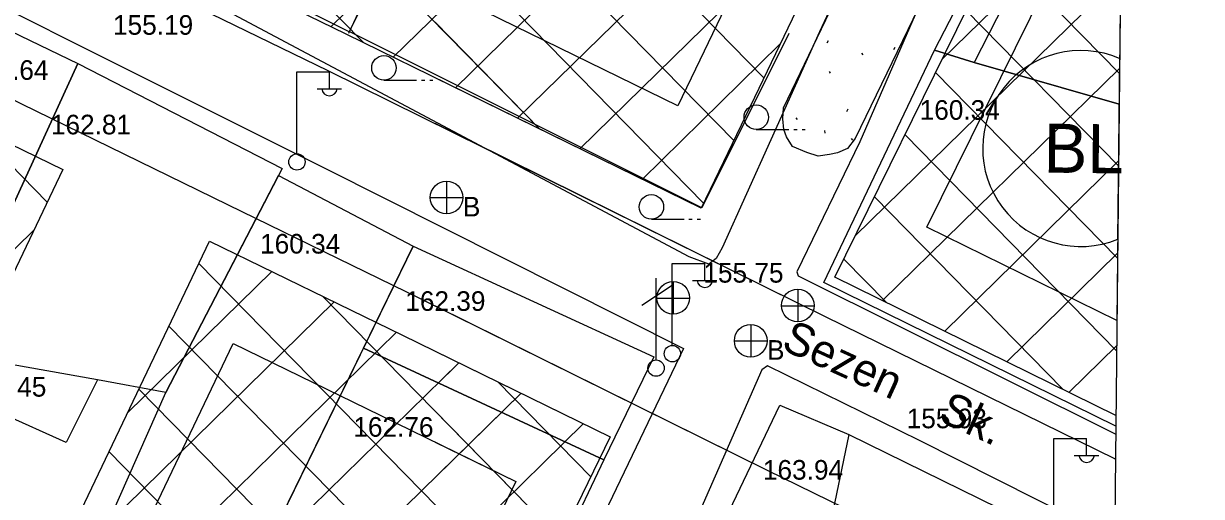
# Model space of a CAD drawing. Extents: x 419677 to 421689, y 4450851 to 4452923.
# Drawn here: x 420633.2 to 420705.3, y 4451724.9 to 4451753.9 of the extents above; entities that cross this region are included whole.
import ezdxf

# ---------------------------------------------------------------- set-up
doc = ezdxf.new("R2010")
doc.units = 0
for name, color, linetype in [('AA_HH', 7, 'Continuous'), ('Level 1', 7, 'Continuous'), ('Level 20', 7, 'Continuous'), ('Level 27', 7, 'Continuous'), ('Level 31', 7, 'Continuous'), ('Level 34', 7, 'Continuous'), ('Level 41', 7, 'Continuous'), ('Level 62', 7, 'Continuous')]:
    doc.layers.add(name, color=color, linetype=linetype)

msp = doc.modelspace()

# ---------------------------------------------------------------- linework, layer by layer
at = {"layer": 'AA_HH'}
for p, q in [((420649.91, 4451745.932), (420649.91, 4451750.932)), ((420649.91, 4451750.932), (420651.91, 4451750.932)), ((420651.91, 4451749.932), (420651.91, 4451750.932)), ((420655.248, 4451750.415), (420657.248, 4451750.415)), ((420657.548, 4451750.415), (420657.748, 4451750.415)), ((420658.048, 4451750.415), (420658.248, 4451750.415)), ((420651.15, 4451749.892), (420652.65, 4451749.892)), ((420678.037, 4451747.395), (420680.037, 4451747.395)), ((420680.337, 4451747.395), (420680.537, 4451747.395)), ((420680.837, 4451747.395), (420681.037, 4451747.395)), ((420659.08, 4451744.231), (420659.08, 4451742.231)), ((420658.08, 4451743.231), (420660.08, 4451743.231)), ((420671.617, 4451741.908), (420673.617, 4451741.908)), ((420673.917, 4451741.908), (420674.117, 4451741.908)), ((420674.417, 4451741.908), (420674.617, 4451741.908)), ((420672.892, 4451734.196), (420672.892, 4451739.196)), ((420672.892, 4451739.196), (420674.892, 4451739.196)), ((420674.892, 4451738.196), (420674.892, 4451739.196)), ((420671.025, 4451736.636), (420672.955, 4451737.906)), ((420671.915, 4451733.286), (420671.915, 4451738.286)), ((420672.97, 4451736.083), (420672.97, 4451738.083)), ((420674.132, 4451738.156), (420675.632, 4451738.156)), ((420671.95, 4451737.073), (420673.95, 4451737.073)), ((420680.591, 4451735.613), (420680.591, 4451737.613)), ((420679.571, 4451736.603), (420681.571, 4451736.603)), ((420677.694, 4451735.46), (420677.694, 4451733.46)), ((420676.694, 4451734.46), (420678.694, 4451734.46)), ((420696.256, 4451723.485), (420696.256, 4451728.485)), ((420696.256, 4451728.485), (420698.256, 4451728.485)), ((420698.256, 4451727.485), (420698.256, 4451728.485)), ((420697.496, 4451727.445), (420698.996, 4451727.445))]:
    msp.add_line(p, q, dxfattribs=at)
for points in [[(420173.096, 4452234.536), (420705.284, 4452228.915), (420698.004, 4451534.891), (420165.768, 4451540.511)], [(420648.295, 4451676.593), (420641.223, 4451662.384), (420640.948, 4451662.031), (420640.508, 4451661.684), (420639.471, 4451661.193), (420638.746, 4451661.186), (420637.534, 4451661.359), (420636.786, 4451661.616), (420584.365, 4451691.657), (420560.63, 4451705.916), (420560.087, 4451706.396), (420559.803, 4451706.768), (420559.709, 4451707.858), (420560.927, 4451712.656), (420582.242, 4451758.178), (420589.137, 4451774.928), (420589.939, 4451775.263), (420617.918, 4451761.909), (420651.635, 4451745.031), (420673.572, 4451733.995), (420661.481, 4451708.765)], [(420636.513, 4451751.427), (420628.393, 4451733.73), (420625.042, 4451735.223), (420626.983, 4451739.07), (420616.108, 4451744.228), (420624.114, 4451757.425)], [(420649.016, 4451745.006), (420641.901, 4451731.298), (420637.717, 4451732.073), (420628.393, 4451733.73), (420636.513, 4451751.427)], [(420657.028, 4451740.247), (420646.913, 4451719.502), (420639.225, 4451723.302), (420638.509, 4451723.641), (420641.901, 4451731.298), (420648.794, 4451744.577)], [(420657.028, 4451740.247), (420671.76, 4451733.483), (420668.7, 4451727.182), (420653.986, 4451734.008)], [(420668.7, 4451727.182), (420661.791, 4451712.61), (420646.913, 4451719.502), (420653.986, 4451734.008)], [(420627.985, 4451731.742), (420621.242, 4451717.589), (420632.959, 4451711.573), (420639.225, 4451723.302), (420638.509, 4451723.641), (420641.901, 4451731.298), (420637.717, 4451732.073), (420635.795, 4451728.243)], [(420695.132, 4451723.104), (420693.277, 4451717.205), (420694.151, 4451716.879), (420692.934, 4451712.965), (420691.908, 4451713.454), (420690.129, 4451708.064), (420686.874, 4451709.515), (420678.21, 4451713.339), (420672.76, 4451716.185), (420674.826, 4451720.778), (420679.47, 4451730.516), (420683.697, 4451728.716)], [(420679.47, 4451730.516), (420683.697, 4451728.716), (420681.53, 4451718.321), (420674.826, 4451720.778)]]:
    msp.add_lwpolyline(points, close=True, dxfattribs=at)
for points in [[(420700.616, 4451783.946), (420684.365, 4451746.633), (420680.51, 4451738.681), (420680.601, 4451738.437), (420700.037, 4451728.745)], [(420695.146, 4451781.793), (420681.899, 4451753.381), (420675.945, 4451740.147), (420675.583, 4451739.5), (420675.132, 4451739.156), (420673.927, 4451739.598), (420644.125, 4451755.472)], [(420663.087, 4451773.536), (420653.124, 4451753.378), (420644.155, 4451757.883)], [(420700.249, 4451748.952), (420691.368, 4451751.492), (420688.935, 4451752.246), (420699.241, 4451772.177), (420700.491, 4451772.027)], [(420700.463, 4451769.316), (420691.368, 4451751.492), (420700.249, 4451748.952)], [(420680.022, 4451753.271), (420674.708, 4451742.607), (420653.112, 4451753.384)], [(420700.043, 4451729.235), (420682.17, 4451738.034), (420688.935, 4451752.246), (420691.368, 4451751.492), (420700.249, 4451748.952)], [(420699.97, 4451722.333), (420688.018, 4451728.351), (420678.731, 4451732.918), (420678.383, 4451732.69), (420658.67, 4451687.779), (420649.079, 4451666.635), (420647.144, 4451660.397), (420646.984, 4451659.823), (420646.876, 4451659.026), (420646.895, 4451658.404), (420647.192, 4451657.734), (420647.879, 4451656.769), (420649.003, 4451655.689), (420652.065, 4451653.381), (420666.641, 4451646.892), (420671.103, 4451645.56), (420671.438, 4451644.757)]]:
    msp.add_lwpolyline(points, dxfattribs=at)
for centre, radius in [((420655.248, 4451751.165), 0.75), ((420678.037, 4451748.145), 0.75), ((420649.92, 4451745.407), 0.5), ((420659.08, 4451743.231), 1), ((420671.617, 4451742.658), 0.75), ((420672.955, 4451737.091), 1), ((420680.575, 4451736.621), 1), ((420677.694, 4451734.46), 1), ((420672.902, 4451733.672), 0.5), ((420671.905, 4451732.786), 0.501)]:
    msp.add_circle(centre, radius, dxfattribs=at)
for centre in [(420651.91, 4451749.935), (420674.892, 4451738.2), (420698.256, 4451727.489)]:
    msp.add_arc(centre, 0.474, 184.83843, 355.14641, dxfattribs=at)
at = {"layer": 'Level 1'}
msp.add_lwpolyline([(420653.094, 4451753.295), (420659.449, 4451766.863), (420661.936, 4451772.145)], dxfattribs=at)
at = {"layer": 'Level 20'}
for points in [[(420682.582, 4451768.29), (420674.58, 4451751.638), (420673.235, 4451748.839)], [(420682.582, 4451768.29), (420674.58, 4451751.638), (420673.235, 4451748.839)], [(420700.11, 4451735.71), (420688.482, 4451741.421), (420698.428, 4451761.571), (420700.372, 4451760.598)], [(420700.11, 4451735.71), (420688.482, 4451741.421), (420698.428, 4451761.571), (420700.372, 4451760.598)], [(420700.372, 4451760.598), (420700.11, 4451735.71)], [(420673.235, 4451748.839), (420658.753, 4451755.946)], [(420673.235, 4451748.839), (420658.753, 4451755.946)], [(420640.31, 4451722.34), (420646.02, 4451734.294)], [(420646.02, 4451734.294), (420654.182, 4451730.311), (420663.324, 4451725.846)], [(420658.373, 4451728.264), (420663.324, 4451725.846)], [(420663.324, 4451725.846), (420661.053, 4451721.162), (420659.275, 4451717.454)], [(420663.324, 4451725.846), (420661.053, 4451721.162), (420659.275, 4451717.454)]]:
    msp.add_lwpolyline(points, dxfattribs=at)
at = {"layer": 'Level 27'}
msp.add_line((420700.049, 4451729.897), (420682.85, 4451738.349), dxfattribs=at)
msp.add_line((420700.049, 4451729.897), (420682.85, 4451738.349), dxfattribs=at)
for points in [[(420698.02, 4451791.59), (420687.354, 4451768.985), (420678.185, 4451749.905), (420674.66, 4451742.57)], [(420698.02, 4451791.59), (420687.354, 4451768.985), (420678.185, 4451749.905), (420674.66, 4451742.57)], [(420682.85, 4451738.349), (420696.412, 4451765.911), (420700.515, 4451774.286)], [(420682.85, 4451738.349), (420696.412, 4451765.911), (420700.515, 4451774.286)], [(420674.66, 4451742.57), (420652.925, 4451753.236), (420642.195, 4451758.464), (420640.315, 4451759.336), (420631.025, 4451763.884), (420628.336, 4451765.146), (420619.63, 4451769.43)], [(420588.3, 4451768.02), (420608.745, 4451758.036), (420621.095, 4451752.014), (420635.592, 4451744.945)], [(420674.66, 4451742.57), (420658.373, 4451750.563)], [(420635.592, 4451744.945), (420628.635, 4451730.385), (420626.405, 4451725.725), (420609.394, 4451733.403), (420599.163, 4451738.124), (420597.92, 4451735.56), (420589.963, 4451719.505), (420594.742, 4451716.488), (420597.726, 4451714.354), (420600.274, 4451712.736)], [(420638.066, 4451712.736), (420640.622, 4451718.135), (420635.442, 4451721.43), (420644.58, 4451740.56)], [(420644.58, 4451740.56), (420656.375, 4451734.804), (420669.1, 4451728.59)], [(420658.373, 4451733.829), (420669.1, 4451728.59)], [(420669.1, 4451728.59), (420664.656, 4451719.425), (420661.515, 4451712.875), (420657.498, 4451703.95)], [(420669.1, 4451728.59), (420664.656, 4451719.425), (420661.515, 4451712.875), (420658.373, 4451705.894)]]:
    msp.add_lwpolyline(points, dxfattribs=at)
at = {"layer": 'Level 31'}
msp.add_lwpolyline([(420700.163, 4451740.676), (420700.279, 4451751.738)], dxfattribs=at)
msp.add_arc((420697.895, 4451746.231), 6, 66.59493, 292.20315, dxfattribs=at)
msp.add_arc((420697.895, 4451746.231), 6, 66.59493, 292.20315, dxfattribs=at)
at = {"layer": 'Level 34'}
for p, q in [((420652.004, 4451753.685), (420693.019, 4451793.868)), ((420655.815, 4451751.818), (420696.92, 4451792.091)), ((420664.78, 4451747.419), (420627.457, 4451785.513)), ((420674.815, 4451742.892), (420633.299, 4451785.266)), ((420674.815, 4451742.892), (420633.299, 4451785.266)), ((420659.623, 4451749.949), (420694.491, 4451784.111)), ((420659.623, 4451749.949), (420694.491, 4451784.111)), ((420653.994, 4451752.711), (420625.599, 4451781.694)), ((420676.657, 4451746.726), (420643.184, 4451780.893)), ((420676.657, 4451746.726), (420643.184, 4451780.893)), ((420678.5, 4451750.561), (420653.348, 4451776.233)), ((420678.5, 4451750.561), (420653.348, 4451776.233)), ((420663.431, 4451748.08), (420689.577, 4451773.697)), ((420663.431, 4451748.08), (420689.577, 4451773.697)), ((420667.239, 4451746.212), (420684.57, 4451763.191)), ((420667.239, 4451746.212), (420684.57, 4451763.191)), ((420689.419, 4451751.699), (420700.391, 4451762.449)), ((420689.419, 4451751.699), (420700.391, 4451762.449)), ((420700.269, 4451750.82), (420692.758, 4451758.486)), ((420700.269, 4451750.82), (420692.758, 4451758.486)), ((420684.099, 4451740.886), (420700.332, 4451756.79)), ((420684.099, 4451740.886), (420700.332, 4451756.79)), ((420700.21, 4451745.164), (420690.886, 4451754.681)), ((420700.21, 4451745.164), (420690.886, 4451754.681)), ((420664.78, 4451747.419), (420658.373, 4451753.959)), ((420671.047, 4451744.343), (420679.484, 4451752.609)), ((420671.047, 4451744.343), (420679.484, 4451752.609)), ((420685.763, 4451736.917), (420700.272, 4451751.133)), ((420685.763, 4451736.917), (420700.272, 4451751.133)), ((420700.15, 4451739.509), (420689.014, 4451750.876)), ((420700.15, 4451739.509), (420689.014, 4451750.876)), ((420634.639, 4451742.951), (420630.026, 4451747.659)), ((420700.091, 4451733.854), (420687.142, 4451747.071)), ((420700.091, 4451733.854), (420687.142, 4451747.071)), ((420689.57, 4451735.047), (420700.213, 4451745.474)), ((420689.57, 4451735.047), (420700.213, 4451745.474)), ((420696.807, 4451731.491), (420685.27, 4451743.267)), ((420696.807, 4451731.491), (420685.27, 4451743.267)), ((420620.645, 4451728.325), (420633.816, 4451741.229)), ((420686.008, 4451736.797), (420683.398, 4451739.462)), ((420686.008, 4451736.797), (420683.398, 4451739.462)), ((420693.376, 4451733.177), (420700.154, 4451739.817)), ((420693.376, 4451733.177), (420700.154, 4451739.817)), ((420639.565, 4451730.062), (420648.385, 4451738.703)), ((420664.206, 4451718.488), (420643.925, 4451739.189)), ((420666.057, 4451722.314), (420651.48, 4451737.193)), ((420636.066, 4451721.033), (420652.2, 4451736.841)), ((420639.531, 4451718.829), (420656.016, 4451734.979)), ((420662.366, 4451714.65), (420642.089, 4451735.346)), ((420697.183, 4451731.306), (420700.094, 4451734.158)), ((420697.183, 4451731.306), (420700.094, 4451734.158)), ((420639.028, 4451712.736), (420659.83, 4451733.117)), ((420658.373, 4451731.689), (420659.83, 4451733.117)), ((420660.568, 4451710.77), (420640.254, 4451731.504)), ((420667.911, 4451726.138), (420662.214, 4451731.953)), ((420667.911, 4451726.138), (420662.214, 4451731.953)), ((420644.743, 4451712.736), (420663.645, 4451731.254)), ((420658.373, 4451726.089), (420663.645, 4451731.254)), ((420666.057, 4451722.314), (420658.373, 4451730.158)), ((420650.459, 4451712.736), (420667.459, 4451729.391)), ((420658.373, 4451720.489), (420667.459, 4451729.391)), ((420653.042, 4451712.736), (420638.419, 4451727.662))]:
    msp.add_line(p, q, dxfattribs=at)
at = {"layer": 'Level 41'}
for p, q in [((420682.383, 4451752.689), (420682.453, 4451752.849)), ((420682.383, 4451752.689), (420682.453, 4451752.849)), ((420686.466, 4451752.281), (420686.537, 4451752.441)), ((420686.466, 4451752.281), (420686.537, 4451752.441)), ((420684.478, 4451752.073), (420684.549, 4451751.967)), ((420684.478, 4451752.073), (420684.549, 4451751.967)), ((420682.492, 4451750.952), (420682.563, 4451750.845)), ((420682.492, 4451750.952), (420682.563, 4451750.845)), ((420683.589, 4451748.498), (420683.66, 4451748.657)), ((420683.589, 4451748.498), (420683.66, 4451748.657)), ((420680.46, 4451748.114), (420680.531, 4451748.007)), ((420680.46, 4451748.114), (420680.531, 4451748.007)), ((420682.218, 4451747.323), (420682.236, 4451747.163)), ((420682.218, 4451747.323), (420682.236, 4451747.163)), ((420683.848, 4451746.853), (420683.918, 4451746.746)), ((420683.848, 4451746.853), (420683.918, 4451746.746))]:
    msp.add_line(p, q, dxfattribs=at)
at = {"layer": 'Level 62'}
msp.add_line((420690.043, 4451759.136), (420684.097, 4451746.846), dxfattribs=at)
msp.add_line((420690.043, 4451759.136), (420684.097, 4451746.846), dxfattribs=at)
for points in [[(420589.397, 4451770.266), (420609.841, 4451760.283), (420622.191, 4451754.261), (420645.676, 4451742.807)], [(420680.53, 4451736.786), (420651.827, 4451750.99), (420641.121, 4451756.206), (420639.239, 4451757.079), (420629.944, 4451761.63), (420627.253, 4451762.893), (420618.526, 4451767.187)], [(420684.097, 4451746.846), (420683.62, 4451746.221), (420682.998, 4451745.968), (420682.527, 4451745.862), (420681.826, 4451745.76), (420681.128, 4451745.987), (420680.252, 4451746.356), (420680.252, 4451746.356), (420679.878, 4451746.949), (420679.722, 4451747.401), (420679.669, 4451748.052), (420679.696, 4451748.721), (420685.898, 4451761.639), (420686.513, 4451762.072), (420687.045, 4451762.267), (420687.665, 4451762.301), (420688.235, 4451762.275), (420688.993, 4451762.107), (420689.433, 4451761.862), (420689.902, 4451761.419), (420690.008, 4451761.052), (420690.221, 4451760.5), (420690.142, 4451760.015), (420690.043, 4451759.136)], [(420684.097, 4451746.846), (420683.62, 4451746.221), (420682.998, 4451745.968), (420682.527, 4451745.862), (420681.826, 4451745.76), (420681.128, 4451745.987), (420680.252, 4451746.356), (420680.252, 4451746.356), (420679.878, 4451746.949), (420679.722, 4451747.401), (420679.669, 4451748.052), (420679.696, 4451748.721), (420685.898, 4451761.639), (420686.513, 4451762.072), (420687.045, 4451762.267), (420687.665, 4451762.301), (420688.235, 4451762.275), (420688.993, 4451762.107), (420689.433, 4451761.862), (420689.902, 4451761.419), (420690.008, 4451761.052), (420690.221, 4451760.5), (420690.142, 4451760.015), (420690.043, 4451759.136)], [(420680.53, 4451736.786), (420658.373, 4451747.751)], [(420645.676, 4451742.807), (420657.472, 4451737.051), (420678.695, 4451726.549)], [(420658.373, 4451736.605), (420678.695, 4451726.549)], [(420682.224, 4451735.948), (420680.53, 4451736.786)], [(420682.224, 4451735.948), (420680.53, 4451736.786)], [(420700.018, 4451727.204), (420682.224, 4451735.948)], [(420700.018, 4451727.204), (420682.224, 4451735.948)], [(420700.021, 4451727.202), (420700.018, 4451727.204)], [(420700.021, 4451727.202), (420700.018, 4451727.204)], [(420678.695, 4451726.549), (420699.475, 4451716.371), (420699.902, 4451716.162)], [(420678.695, 4451726.549), (420699.475, 4451716.371), (420699.902, 4451716.162)]]:
    msp.add_lwpolyline(points, dxfattribs=at)

# ---------------------------------------------------------------- texts
at = {"layer": 'AA_HH'}
for s, height, rotation, p in [('155.19 ', 1.2, 359.99814, (420638.662, 4451753.194)), ('155.75 ', 1.2, 359.99814, (420674.797, 4451738.021)), ('Sezen    Sk.', 2, 335.50668, (420679.489, 4451733.977)), ('155.93 ', 1.2, 359.99814, (420687.242, 4451729.106))]:
    msp.add_text(s, height=height, rotation=rotation, dxfattribs=at).set_placement(p)
for s, p in [('164.64', (420629.806, 4451750.434)), ('160.34 ', (420688.034, 4451747.99)), ('162.81', (420634.861, 4451747.097)), ('B', (420660.08, 4451742.07)), ('160.34', (420647.665, 4451739.799)), ('162.39', (420656.553, 4451736.291)), ('B', (420678.694, 4451733.299)), ('164.45', (420629.677, 4451731.042)), ('162.76', (420653.373, 4451728.589)), ('163.94 ', (420678.442, 4451725.961))]:
    msp.add_text(s, height=1.2, dxfattribs=at).set_placement(p)
at = {"layer": 'Level 31'}
msp.add_text('BL', height=3, rotation=359.41414, dxfattribs=at).set_placement((420695.612, 4451744.754))
msp.add_text('BL', height=3, rotation=359.41414, dxfattribs=at).set_placement((420695.612, 4451744.754))

doc.saveas('drawing.dxf')
